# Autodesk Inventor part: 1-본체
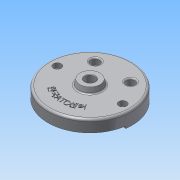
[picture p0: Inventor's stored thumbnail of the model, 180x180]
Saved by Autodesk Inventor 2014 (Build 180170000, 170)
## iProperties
Created: 2015-06
Part Number: 1-본체
Material: 알루미늄 6061
Document SubType Name: Modeling
Designer: Administrator
Density: 2.71 g/cm^3
Appearance: 알루미늄 - 평지
Mass: 1066.82 g
Surface Area: 1033.37 cm^2
Volume: 393.662 cm^3
Author: Administrator
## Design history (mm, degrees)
sketch "스케치1"
  geometry: C1 r 95 at (0, 0); 1 further point
  constraints: 1 centre point, 1 coincident
  dimensions: "d0" = 190 diameter of C1
extrude "돌출1" new body sketch "스케치1" distance "d1" = 32; taper "d2" = 0 deg
feature "쉘1" dims "d3" = 7, "d4" = 5
sketch "스케치2"
  geometry: C1 r 90 at (0, 0) reference; C2 r 15 at (-40, 52); C3 r 15 at (40, 52)
  constraints: 2 centre point, 1 equal radius
  dimensions: "d5" = 30 diameter of C2; "d6" = 40 horizontal distance of C1.centre C2.centre; "d7" = 40 horizontal distance of C1.centre C3.centre; "d8" = 52 vertical distance of C1.centre C2.centre; "d9" = 52 vertical distance of C1.centre C3.centre
extrude "돌출2" join sketch "스케치2" stored distance "d10" = 32; taper "d11" = 0 deg
sketch "스케치3"
  geometry: L1 (-6, -13.748)-(-6, 13.748); L2 (6, -13.748)-(6, 13.748); L3 (66.252, 6)-(93.748, 6); L4 (66.252, -6)-(93.748, -6); A1 r 15 centre (0, 0) between (-6, -13.748) and (-6, 13.748) reference; A2 r 15 centre (80, 0) between (66.252, 6) and (93.748, 6) reference; 1 further point
  constraints: 8 end point, 8 point on circle, 4 parallel, 1 perpendicular, 1 vertical
  dimensions: "d12" = 6 distance from line of A1.centre L1; "d13" = 12 distance between parallel lines of L4 L3
extrude "돌출3" cut sketch "스케치3" distance "d14" = 3; taper "d15" = 0 deg
sketch "스케치4"
  geometry: A1 r 15 centre (0, 0) between (-6, 13.748) and (-6, -13.748) reference; A2 r 15 centre (80, 0) between (93.748, 6) and (66.252, 6) reference; 3 further points
  constraints: 2 coincident
hole "구멍1" sketch "스케치4" at (0, 0), (80, 0) diameter "d16" = 20; stored, may be unused: countersink angle "d20" = 90 deg, drill point angle "d22" = 118 deg; dims "d17" = 6, "d18" = 4, "d19" = 2, "d21" = 8
sketch "스케치5"
  geometry: L1 (45.033, 16)-(75.657, 16); L2 (-75.657, 16)-(-45.033, 16); A1 r 90 centre (0, 0) between (-88.566, 16) and (88.566, 16) reference; A2 r 90 centre (0, 0) between (85.114, 29.25) and (-85.114, 29.25); A3 r 10 centre (-75.657, 26) between (-85.114, 29.25) and (-75.657, 16); A4 r 10 centre (75.657, 26) between (75.657, 16) and (85.114, 29.25); A5 r 42 centre (0, 0) between (36.373, 21) and (-36.373, 21); A6 r 10 centre (-45.033, 26) between (-45.033, 16) and (-36.373, 21); A7 r 10 centre (45.033, 26) between (36.373, 21) and (45.033, 16); 2 further points
  constraints: 18 point on circle, 10 tangent, 6 centre point, 6 point on line, 5 end point, 2 coincident, 1 collinear, 1 equal radius, 1 horizontal
  dimensions: "d23" = 16 distance from line of L1 A1.centre; "d24" = 10 radius of A3; "d25" = 84 diameter of A5; "d26" = 10 radius of A6; "d27" = 10 radius of A7
extrude "돌출4" join sketch "스케치5" distance "d28" = 7; taper "d29" = 0 deg
sketch "스케치6"
  geometry: C1 r 35 at (0, 0); A1 r 90 centre (0, 0) between (-85.114, 29.25) and (85.114, 29.25) reference
  constraints: 1 centre point, 1 coincident
  dimensions: "d30" = 70 diameter of C1
extrude "돌출5" join sketch "스케치6" distance "d31" = 10; taper "d32" = -10 deg
sketch "스케치7"
  geometry: L1 (0, 0)-(-94.075, -13.221); L2 (0, 0)-(94.075, -13.221); L3 (-95, 0)-(-90, 0); L4 (-35, 0)-(0, 0); L5 (0, 0)-(35, 0); L6 (90, 0)-(95, 0); A1 r 90 centre (0, 0) between (-90, 0) and (90, 0) reference; A2 r 95 centre (0, 0) between (-95, 0) and (-94.075, -13.221) reference; A3 r 35 centre (0, 0) between (-35, 0) and (35, 0) reference; A4 r 95 centre (0, 0) between (-94.075, -13.221) and (94.075, -13.221)
  constraints: 12 end point, 10 point on circle, 6 collinear, 2 horizontal, 1 centre point, 1 coincident
  dimensions: "d35" = 8 deg angle of L1 L3; "d36" = 8 deg angle of L2 L6
extrude "돌출6" cut sketch "스케치7" distance "d37" = 5; taper "d38" = 0 deg
sketch "스케치8"
  geometry: L1 (-45.033, 16)-(-75.657, 16) reference; L2 (-87.972, -19)-(87.972, -19); L3 (0, 0)-(0, -19); L4 (-87.972, -14)-(87.972, -14); L5 (-59, -19)-(-59, -14); L6 (-41, -19)-(-41, -14); L7 (41, -19)-(41, -14); L8 (59, -19)-(59, -14); C1 r 35 at (0, 0) reference; A1 r 90 centre (0, 0) between (-85.114, 29.25) and (85.114, 29.25) reference; A2 r 41 centre (0, -19) between (-41, -19) and (41, -19); A3 r 59 centre (0, -19) between (-59, -19) and (59, -19); A4 r 9 centre (-50, -14) between (-41, -14) and (-59, -14); A5 r 9 centre (50, -14) between (59, -14) and (41, -14)
  constraints: 14 end point, 10 point on circle, 8 point on line, 8 tangent, 4 centre point, 3 parallel, 3 perpendicular, 2 coincident, 1 midpoint
  dimensions: "d39" = 19 distance from line of L2 C1.centre; "d40" = 41 radius of A2; "d41" = 59 radius of A3; "d42" = 5 distance between parallel lines of L2 L4
extrude "돌출7" cut sketch "스케치8" distance "d43" = 7; taper "d44" = 0 deg
sketch "스케치9"
  geometry: C1 r 35 at (0, 0) reference; C2 r 9 at (-74, 0); C3 r 9 at (74, 0); A1 r 42 centre (0, 0) between (36.373, 21) and (-36.373, 21) reference; A2 r 15 centre (-40, 52) between (-34, 65.748) and (-46, 65.748) reference; A3 r 15 centre (40, 52) between (26.252, 58) and (26.252, 46) reference
  constraints: 2 centre point, 2 horizontal alignment, 1 equal radius
  dimensions: "d45" = 18 diameter of C2; "d47" = 74 distance of C1.centre C2.centre; "d48" = 74 distance of C3.centre A1.centre
extrude "돌출8" join sketch "스케치9" stored distance "d49" = 7; taper "d50" = 0 deg
sketch "스케치10"
  geometry: C1 r 9 at (-74, 0) reference; C2 r 9 at (74, 0) reference; 2 further points
  constraints: 2 coincident
hole "구멍2" sketch "스케치10" at (-74, 0), (74, 0) diameter "d51" = 11; stored, may be unused: countersink angle "d55" = 90 deg, drill point angle "d57" = 118 deg; dims "d52" = 6, "d53" = 18, "d54" = 11, "d56" = 8
sketch "스케치11"
  geometry: C1 r 95 at (0, 0) reference; C2 r 26 at (0, 0)
  constraints: 1 centre point, 1 coincident
  dimensions: "d69" = 52 diameter of C2
extrude "돌출9" join sketch "스케치11" distance "d70" = 12; taper "d71" = -15 deg
sketch "스케치12"
  geometry: C1 r 95 at (0, 0) reference; C2 r 68 at (0, 0)
  constraints: 1 centre point, 1 coincident, 1 other
  dimensions: "d72" = 136 diameter of C2
feature "엠보싱1" sketch "스케치12" dims "d73" = 0.5, "d74" = 0
fillet "모깎기1" dims "d75" = 3
fillet "모깎기2" dims "d76" = 3
fillet "모깎기3" dims "d77" = 5
fillet "모깎기4" dims "d78" = 1
fillet "모깎기5" dims "d79" = 3
fillet "모깎기6" dims "d80" = 3
chamfer "모따기1" distance "d81" = 1; stored, may be unused: second distance "d82" = 2, angle "d83" = 45 deg
fillet "모깎기7" dims "d84" = 3
hole "구멍5" diameter "d97" = 23; stored, may be unused: countersink angle "d101" = 90 deg, drill point angle "d103" = 118 deg; dims "d95" = 10, "d96" = 10, "d98" = 6, "d99" = 50, "d100" = 15, "d102" = 8
chamfer "모따기2" distance "d104" = 1; stored, may be unused: second distance "d105" = 2, angle "d106" = 45 deg
fillet "모깎기9" dims "d107" = 0.3
node "솔리드1"
other parameters: "d33" = 5 deg, "d34" = 5 deg
